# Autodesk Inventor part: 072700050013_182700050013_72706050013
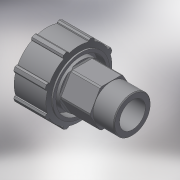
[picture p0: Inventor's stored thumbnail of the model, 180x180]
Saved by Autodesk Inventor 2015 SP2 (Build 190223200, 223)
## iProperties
Created: 2017-04
Part Number: 072700050013_182700050013_72706050013
Material: Generic
Description: PLASSON BRASS THREADED ADAPTOR 50-1.1/4"
Document SubType Name: Modeling
Designer: KIM
Density: 1 g/cm^3
Appearance: Default
Author: KIM
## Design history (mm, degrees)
derived "07270.ipt"
feature "Solid1::07270.ipt"
tag "TaggingFeature1"
body "Solid1"
other parameters: "d1" = 41.91, "d2" = 95, "d3" = 21, "d7" = 96, "d8" = 76.8, "d12" = 29.337, "d13" = 33.528, "d15" = 72, "d17" = 38, "d18" = 21, "d19" = 25.2, "d40" = 52, "d41" = 59.8, "d42" = 135 deg, "d43" = 100 deg, "d44" = 34.96, "d45" = 68.4, "d46" = 89.28, "d47" = 35 deg, "d48" = 17.5 deg, "d50" = 0, "d52" = 360 deg, "d54" = 1.92, "d57" = 1.92, "d61" = 0, "d62" = 0.8382, "d65" = 1.2573, "R_" = 41.91, "E_" = 96, "H_" = 95, "l_2" = 21, "Wrench" = 52
